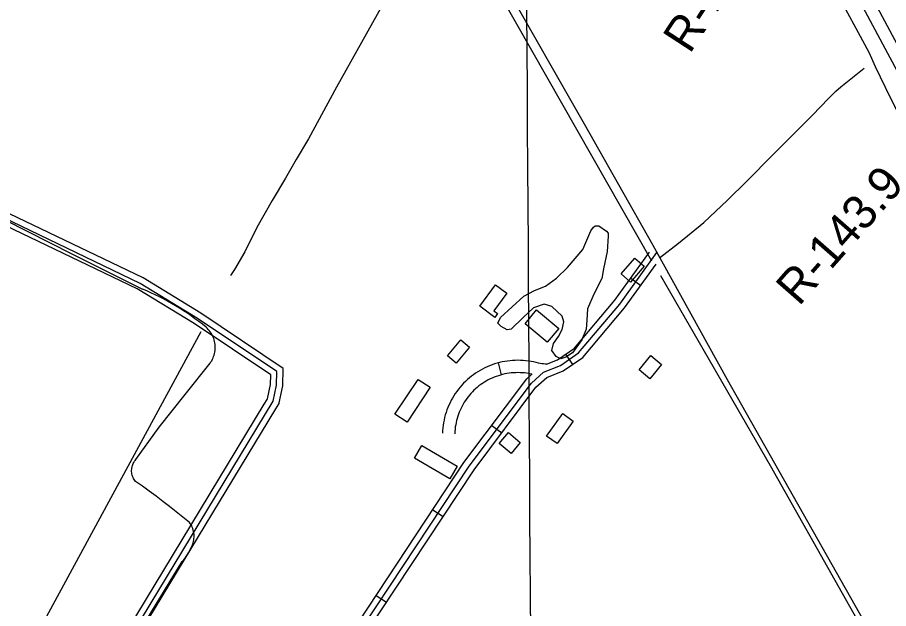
# Model space of a CAD drawing. Extents: x 3477039 to 3515015, y 546746 to 572297.
# Drawn here: x 3495798 to 3497919, y 559836 to 561275 of the extents above; entities that cross this region are included whole.
import ezdxf

# ---------------------------------------------------------------- set-up
doc = ezdxf.new("R2010")
doc.units = 0
for name, color, linetype in [('V-BLDG-OTLN', 7, 'Continuous'), ('V-DTCH-CNTR', 7, 'Continuous'), ('V-GRID-MAJR', 7, 'Continuous'), ('V-LEVE-TOET', 7, 'Continuous'), ('V-RIVR-RANG-IDEN', 7, 'Continuous'), ('V-ROAD-CNTR', 7, 'Continuous'), ('V-SITE-VEGE', 7, 'Continuous'), ('V-SURV-LINE', 7, 'Continuous'), ('V-TOPO-SHOR', 7, 'Continuous')]:
    doc.layers.add(name, color=color, linetype=linetype)

msp = doc.modelspace()

# ---------------------------------------------------------------- linework, layer by layer
at = {"layer": 'V-BLDG-OTLN'}
for points in [[(3497301.024, 560689.051), (3497323.892, 560669.183), (3497290.3740000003, 560630.562), (3497267.484, 560650.452)], [(3496962.037, 560623.654), (3496989.349, 560603.504), (3496957.798, 560560.733), (3496967.11, 560553.8640000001), (3496960.37, 560544.728), (3496923.7460000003, 560571.747)], [(3497061.795, 560563.387), (3497115.801, 560517.903), (3497087.342, 560484.115), (3497033.899, 560529.126)], [(3496877.377, 560489.733), (3496898.43, 560471.973), (3496865.953, 560433.464), (3496844.895, 560451.227)], [(3497339.983, 560451.72), (3497366.4760000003, 560430.267), (3497338.052, 560395.165), (3497311.559, 560416.617)], [(3496773.861, 560393.545), (3496802.594, 560374.777), (3496746.71, 560289.22), (3496716.758, 560308.745)], [(3497125.56, 560310.341), (3497150.951, 560292.158), (3497111.83, 560237.524), (3497086.4390000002, 560255.706)], [(3496993.216, 560264.0970000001), (3497022.074, 560240.02), (3496999.7430000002, 560213.255), (3496970.884, 560237.329)], [(3496782.5810000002, 560232.818), (3496868.501, 560182.537), (3496850.478, 560151.743), (3496764.561, 560202.026)]]:
    msp.add_lwpolyline(points, close=True, dxfattribs=at)
at = {"layer": 'V-DTCH-CNTR'}
for points in [[(3494934.281, 561194.456), (3495099.7660000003, 561118.701), (3495285.64, 561022.8420000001), (3495458.068, 560933.539), (3495563.661, 560881.53), (3495712.159, 560809.422), (3495931.952, 560698.639), (3496102.063, 560613.461)], [(3497361.526, 560689.696), (3497407.7600000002, 560725.054), (3497469.302, 560775.54), (3497527.154, 560829.756), (3497574.194, 560876.246), (3497637.304, 560940.455), (3497734.006, 561036.756), (3497772.478, 561077.726), (3497790.4, 561095.435), (3497803.083, 561106.126), (3497859.768, 561151.442)], [(3496143.253, 560594.615), (3496133.086, 560599.612), (3496122.832, 560604.419), (3496112.49, 560609.035), (3496102.063, 560613.461)], [(3496272.568, 560442.555), (3496274.128, 560445.937), (3496275.492, 560449.402), (3496276.6550000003, 560452.941), (3496277.614, 560456.539), (3496278.365, 560460.189), (3496278.906, 560463.873), (3496279.238, 560467.584), (3496279.353, 560471.305), (3496279.256, 560475.028), (3496278.947, 560478.7390000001), (3496278.427, 560482.428), (3496277.694, 560486.079), (3496276.756, 560489.684), (3496275.611, 560493.229), (3496274.265, 560496.702), (3496272.723, 560500.0920000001), (3496270.991, 560503.389), (3496269.072, 560506.582), (3496266.974, 560509.658), (3496264.701, 560512.609), (3496262.2660000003, 560515.427), (3496259.671, 560518.102), (3496256.929, 560520.621), (3496248.114, 560527.732), (3496239.169, 560534.679), (3496230.094, 560541.457), (3496220.899, 560548.068), (3496211.58, 560554.507), (3496202.145, 560560.774), (3496192.595, 560566.865), (3496182.937, 560572.777), (3496173.168, 560578.512), (3496163.296, 560584.064), (3496153.323, 560589.432), (3496143.253, 560594.615)], [(3496072.056, 559743.09), (3496199.13, 559950.421), (3496202.534, 559954.478), (3496205.778, 559958.666), (3496208.858, 559962.977), (3496211.769, 559967.403), (3496214.505, 559971.939), (3496217.065, 559976.576), (3496219.4420000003, 559981.311), (3496221.636, 559986.132), (3496223.6410000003, 559991.035), (3496225.453, 559996.012), (3496226.379, 559999.389), (3496227.088, 560002.817), (3496227.575, 560006.284), (3496227.8370000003, 560009.776), (3496227.878, 560013.276), (3496227.696, 560016.774), (3496227.288, 560020.252), (3496226.662, 560023.696), (3496225.8140000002, 560027.094), (3496224.753, 560030.432), (3496223.4790000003, 560033.6950000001), (3496221.998, 560036.8690000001), (3496220.319, 560039.943), (3496218.447, 560042.905), (3496216.389, 560045.7390000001), (3496200.433, 560058.7660000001), (3496184.344, 560071.632), (3496168.126, 560084.334), (3496151.776, 560096.8690000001), (3496135.302, 560109.2390000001), (3496118.703, 560121.441), (3496101.981, 560133.473), (3496085.139, 560145.335), (3496083.386, 560147.658), (3496081.798, 560150.0970000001), (3496080.383, 560152.638), (3496079.15, 560155.272), (3496078.1040000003, 560157.988), (3496077.248, 560160.767), (3496076.588, 560163.601), (3496076.127, 560166.475), (3496075.865, 560169.373), (3496075.808, 560172.281), (3496075.951, 560175.187), (3496076.2970000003, 560178.0750000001), (3496076.844, 560180.934), (3496077.588, 560183.746), (3496078.526, 560186.5), (3496079.6520000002, 560189.183), (3496080.963, 560191.78), (3496082.452, 560194.28), (3496084.111, 560196.67), (3496085.931, 560198.9400000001), (3496142.935, 560277.804), (3496206.335, 560357.125), (3496266.7660000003, 560433.02), (3496268.881, 560436.086), (3496270.816, 560439.2660000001), (3496272.568, 560442.555)]]:
    msp.add_lwpolyline(points, dxfattribs=at)
at = {"layer": 'V-GRID-MAJR'}
msp.add_spline([(3497073.037565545, 555496.0515890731), (3497056.56, 558259.177), (3497020.416, 564320.132), (3496984.272, 570381.104), (3496984.251, 570384.554)], degree=3, dxfattribs=at)
at = {"layer": 'V-LEVE-TOET'}
msp.add_lwpolyline([(3497488.9280000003, 561891.532), (3497592.856, 561713.321), (3497695.362, 561517.182), (3497787.512, 561344.726), (3497870.5810000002, 561189.823), (3497886.562, 561155.61), (3497922.856, 561079.719), (3497970.409, 560984.5160000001), (3498039.598, 560849.8150000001), (3498106.674, 560727.375), (3498169.001, 560615.462), (3498239.082, 560483.38), (3498302.2090000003, 560359.212), (3498381.41, 560215.705), (3498491.829, 560026.082), (3498597.078, 559849.612), (3498655.131, 559754.784)], dxfattribs=at)
at = {"layer": 'V-ROAD-CNTR'}
for p, q in [((3497291.225379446, 560639.939693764), (3497315.5983307, 560622.4477287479)), ((3497132.55369679, 560454.9510637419), (3497149.6086626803, 560430.271113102)), ((3496976.6787186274, 560404.9783419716), (3496968.9567599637, 560433.9675012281)), ((3496953.065055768, 560281.7784100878), (3496977.057007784, 560263.76744611)), ((3496809.198343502, 560076.3568209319), (3496834.230293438, 560059.821854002)), ((3496671.4006190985, 559867.7632381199), (3496696.4325690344, 559851.2272711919))]:
    msp.add_line(p, q, dxfattribs=at)
for points in [[(3495784.929392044, 562855.149263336), (3495836.687288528, 562830.8483119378), (3495887.869186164, 562796.0653815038), (3495994.9209720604, 562699.1955752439), (3496169.52062286, 562546.5178806), (3496324.772312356, 562410.131153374), (3496416.298129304, 562312.184349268), (3496470.894020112, 562245.1824832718), (3496524.223913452, 562166.701640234), (3496592.42477705, 562048.896875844), (3496710.395541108, 561850.2872730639), (3496849.4982629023, 561594.8367839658), (3496981.761998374, 561359.3132550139), (3497177.7296064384, 561015.543942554), (3497344.6122726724, 560720.2865330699), (3497526.0809097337, 560393.234187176), (3497906.739148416, 559720.832531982)], [(3496429.692102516, 560412.7001482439), (3496236.194489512, 560542.2058892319), (3496096.7527683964, 560627.3867188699), (3495694.443573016, 560819.8133340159), (3495557.0028478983, 560890.7201922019), (3495111.790738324, 561124.0807254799), (3494882.466196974, 561244.7624841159), (3494954.2360534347, 561429.9081138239), (3495006.566948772, 561556.9138598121), (3495031.1358996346, 561620.8427319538)], [(3496884.9791919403, 561531.6549103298), (3496981.761998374, 561359.3132550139), (3497177.7296064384, 561015.543942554), (3497344.6122726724, 560720.2865330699), (3497526.0809097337, 560393.234187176), (3497906.739148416, 559720.832531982), (3498102.6447566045, 559404.3021650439), (3498398.9351640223, 558897.4921786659), (3498714.302533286, 558355.897261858), (3498913.399135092, 558032.1899092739), (3499011.1859395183, 557897.511178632), (3499269.5474227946, 557543.9508857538), (3499385.340191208, 557402.6591683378), (3499670.8446201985, 557083.6958062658), (3499981.2859993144, 556735.7635021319), (3500083.10779567, 556622.88472789), (3500127.46270696, 556569.357834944), (3500201.255559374, 556502.8429679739), (3500336.9632879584, 556381.5222106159), (3500543.129875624, 556217.396538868), (3500745.793470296, 556030.2749131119)], [(3496444.881072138, 560420.5841324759), (3496244.279473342, 560554.8448639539), (3496103.917754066, 560640.587692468), (3495701.119559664, 560833.247307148), (3495591.788778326, 560889.6521943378)], [(3496414.503132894, 560404.816164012), (3496228.1095056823, 560529.56691451), (3496089.587782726, 560614.185745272), (3495687.767586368, 560806.379360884), (3495578.0688057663, 560862.974247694)], [(3496242.4924769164, 559192.305589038), (3496478.044005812, 559547.851877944), (3496897.325167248, 560182.546608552), (3497049.19386351, 560384.8422039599), (3497078.826804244, 560411.50715063), (3497119.7947223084, 560427.901117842), (3497164.114633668, 560458.5280565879), (3497264.4464330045, 560576.899819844), (3497354.527252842, 560702.4175688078)], [(3497086.304936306, 560430.6557441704), (3497112.655736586, 560441.200091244), (3497153.954653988, 560469.7400341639), (3497252.612456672, 560586.13680137), (3497336.8572881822, 560703.5225665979)], [(3496262.7464364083, 559195.7175822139), (3496490.553980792, 559539.5758944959), (3496909.592142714, 560173.9016258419), (3497060.3128412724, 560374.6692243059), (3497086.876788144, 560398.5721764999), (3497126.93370803, 560414.6021444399), (3497174.2746133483, 560447.3160790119), (3497276.280409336, 560567.6628383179), (3497352.9032560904, 560674.4276247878)], [(3497085.9720192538, 560430.9058553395), (3497082.8890452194, 560430.9708597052), (3497078.6683167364, 560431.241907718), (3497074.4700130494, 560431.698583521), (3497070.286361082, 560432.3396898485), (3497066.3204542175, 560433.1245916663), (3497060.875983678, 560434.5964840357), (3497054.624862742, 560436.0544619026), (3497048.328377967, 560437.2928468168), (3497041.9877642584, 560438.3102206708), (3497035.6191412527, 560439.1042562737), (3497029.2298810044, 560439.6745121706), (3497022.821537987, 560440.025206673), (3497016.3999697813, 560440.1472731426), (3497009.984314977, 560440.0449709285), (3497003.576241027, 560439.7216277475), (3496997.179566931, 560439.1725008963), (3496990.8069072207, 560438.3991991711), (3496984.466573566, 560437.4039965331), (3496978.168561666, 560436.1890300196), (3496971.9135568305, 560434.7551150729), (3496965.707256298, 560433.1019178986), (3496959.567499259, 560431.23026648), (3496953.4981619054, 560429.1505330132), (3496947.5025094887, 560426.8546501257), (3496941.592394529, 560424.3547194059), (3496935.7738361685, 560421.6474508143), (3496930.0518792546, 560418.7401958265), (3496924.433518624, 560415.6319579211), (3496918.9317124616, 560412.3310920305), (3496913.5450636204, 560408.8383741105), (3496908.2867862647, 560405.1600844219), (3496903.156686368, 560401.299714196), (3496898.1681016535, 560397.2628917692), (3496893.3255044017, 560393.058280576), (3496888.6261288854, 560388.6803323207), (3496884.0877556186, 560384.1419590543), (3496879.7098561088, 560379.4516634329), (3496875.497006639, 560374.6080304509), (3496871.4566821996, 560369.6188997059), (3496867.595158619, 560364.4934266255), (3496863.91455033, 560359.2386806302), (3496860.4183603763, 560353.8560729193), (3496857.1130847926, 560348.3541776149), (3496854.0000399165, 560342.7371855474), (3496851.091096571, 560337.0183684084), (3496848.378928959, 560331.2031587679), (3496845.872845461, 560325.288801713), (3496843.57746009, 560319.2994675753), (3496841.489398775, 560313.2302564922), (3496839.6177524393, 560307.0902106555), (3496837.961328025, 560300.8911347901), (3496836.5199408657, 560294.6353184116), (3496835.3023454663, 560288.3317028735), (3496834.3028481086, 560281.9950202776), (3496833.5273414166, 560275.6210523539), (3496832.974296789, 560269.2316450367), (3496832.6578355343, 560263.0841501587)], [(3495900.937160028, 559482.1420093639), (3496420.673120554, 560340.7722921), (3496428.921104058, 560379.7582141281), (3496429.692102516, 560412.7001482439)], [(3496239.132483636, 559214.393544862), (3496465.5340308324, 559556.127861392), (3496885.058191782, 560191.1915912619), (3497038.074885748, 560395.015183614), (3497051.248027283, 560406.8690774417)], [(3496405.531150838, 560344.7242841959), (3496406.5241488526, 560346.3642809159), (3496413.9581339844, 560381.5012106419), (3496414.503132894, 560404.816164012)], [(3496435.1830915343, 560336.8882998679), (3496443.884074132, 560378.0152176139), (3496444.881072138, 560420.5841324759)], [(3497050.555077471, 560406.1985058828), (3497048.3211372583, 560406.7195380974), (3497043.0556220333, 560407.7551531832), (3497037.7542357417, 560408.6057793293), (3497032.4288587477, 560409.2697437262), (3497027.076118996, 560409.7474878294), (3497021.7164620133, 560410.0407933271), (3497016.354030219, 560410.1427268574), (3497010.979685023, 560410.0570290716), (3497005.615758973, 560409.7863722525), (3497000.270433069, 560409.3274991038), (3496994.9410927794, 560408.680800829), (3496989.635426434, 560407.8480034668), (3496984.3634383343, 560406.8309699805), (3496979.12844317, 560405.630884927), (3496973.944743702, 560404.2500821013), (3496968.8065007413, 560402.6837335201), (3496963.727838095, 560400.9434669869), (3496958.7134905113, 560399.0233498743), (3496953.7676054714, 560396.9312805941), (3496948.9001638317, 560394.6665491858), (3496944.1121207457, 560392.2338041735), (3496939.416481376, 560389.636042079), (3496934.8142875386, 560386.8749079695), (3496930.3089363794, 560383.9536258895), (3496925.9092137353, 560380.8759155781), (3496921.6173136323, 560377.646285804), (3496917.4438983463, 560374.2691082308), (3496913.3904955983, 560370.749719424), (3496909.463871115, 560367.0916676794), (3496905.6662443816, 560363.2940409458), (3496902.000143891, 560359.3663365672), (3496898.478993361, 560355.3179695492), (3496895.1013178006, 560351.1471002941), (3496891.8688413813, 560346.8565733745), (3496888.78744967, 560342.4573193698), (3496885.863639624, 560337.9559270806), (3496883.0989152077, 560333.3538223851), (3496880.4979600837, 560328.6608144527), (3496878.062903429, 560323.8736315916), (3496875.7930710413, 560319.0068412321), (3496873.699154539, 560314.065198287), (3496871.77653991, 560309.0485324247), (3496870.030601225, 560303.9737435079), (3496868.4662475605, 560298.8417893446), (3496867.078671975, 560293.6488652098), (3496865.8740591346, 560288.4206815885), (3496864.855654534, 560283.1482971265), (3496864.0191518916, 560277.8449797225), (3496863.370658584, 560272.5149476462), (3496862.907703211, 560267.1663549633), (3496862.6181644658, 560261.5418498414)], [(3496398.77516435, 560333.5633065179), (3496405.531150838, 560344.7242841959)], [(3495885.4891909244, 559486.401000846), (3495888.432185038, 559490.449992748), (3496398.77516435, 560333.5633065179)], [(3495911.017139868, 559469.8280339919), (3496426.9631079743, 560322.1973292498)], [(3496426.9631079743, 560322.1973292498), (3496434.822092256, 560335.180303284), (3496435.094091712, 560336.464300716)]]:
    msp.add_lwpolyline(points, dxfattribs=at)
at = {"layer": 'V-SITE-VEGE'}
msp.add_lwpolyline([(3496974.239, 560544.593), (3497030.866, 560596.485), (3497057.046, 560610.08), (3497083.215, 560620.924), (3497110.802, 560640.005), (3497137.057, 560665.964), (3497174.398, 560709.721), (3497193.889, 560754.953), (3497200.813, 560764.534), (3497204.948, 560767.258), (3497213.193, 560767.211), (3497232.359, 560754.736), (3497236.451, 560749.219), (3497236.412, 560742.35), (3497233.454, 560705.267), (3497224.971, 560662.719), (3497220.718, 560639.387), (3497201.268, 560601.023), (3497185.953, 560565.388), (3497184.423, 560537.914), (3497182.926, 560515.939), (3497171.787, 560489.897), (3497149.628, 560458.417), (3497133.078, 560447.52), (3497120.6890000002, 560443.4670000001), (3497109.728, 560449.025), (3497098.821, 560464.201), (3497103.036, 560480.665), (3497115.502, 560498.456), (3497123.8370000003, 560514.897), (3497128.068, 560534.109), (3497124.026, 560547.872), (3497099.4250000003, 560571.368), (3497080.219, 560576.974), (3497054.06, 560567.502), (3497029.197, 560544.284), (3497000.183, 560515.593), (3496990.557, 560514.272), (3496975.49, 560522.601), (3496967.292, 560530.892)], close=True, dxfattribs=at)
at = {"layer": 'V-SURV-LINE'}
for points in [[(3497666.4135172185, 561719.5667040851), (3498473.85465832, 560212.5805583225)], [(3498447.4012755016, 560198.430682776), (3497639.9599622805, 561705.4171497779)]]:
    msp.add_lwpolyline(points, dxfattribs=at)
at = {"layer": 'V-TOPO-SHOR'}
for p, q in [((3496605.343119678, 561975.3498394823), (3497342.0236970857, 560682.547649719)), ((3496244.2251895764, 560509.2110432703), (3495326.9856471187, 558819.1791303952))]:
    msp.add_line(p, q, dxfattribs=at)
for points in [[(3496847.077, 561536.677), (3496815.034, 561516.082), (3496806.088, 561509.455), (3496801.607, 561505.025), (3496782.898, 561479.898), (3496754.37, 561425.876), (3496635.821, 561213.527), (3496574.306, 561104.768), (3496506.75, 560978.9720000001), (3496476.757, 560928.671), (3496450.508, 560883.5430000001), (3496418.264, 560828.802), (3496380.761, 560763.698), (3496351.4590000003, 560704.484), (3496325.965, 560661.581), (3496316.227, 560646.79)], [(3497363.690772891, 560646.4358567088), (3497630.9180411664, 560184.204906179), (3498042.5924814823, 559454.7466873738)]]:
    msp.add_lwpolyline(points, dxfattribs=at)

# ---------------------------------------------------------------- texts
at = {"layer": 'V-RIVR-RANG-IDEN'}
for s, height, rotation, p in [('R-144.1', 82.99999799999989, 56.9048385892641, (3497434.886, 561183.904)), ('R-143.9', 82.999998, 48.79390164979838, (3497700.731, 560569.779))]:
    msp.add_text(s, height=height, rotation=rotation, dxfattribs=at).set_placement(p)

doc.saveas('drawing.dxf')
